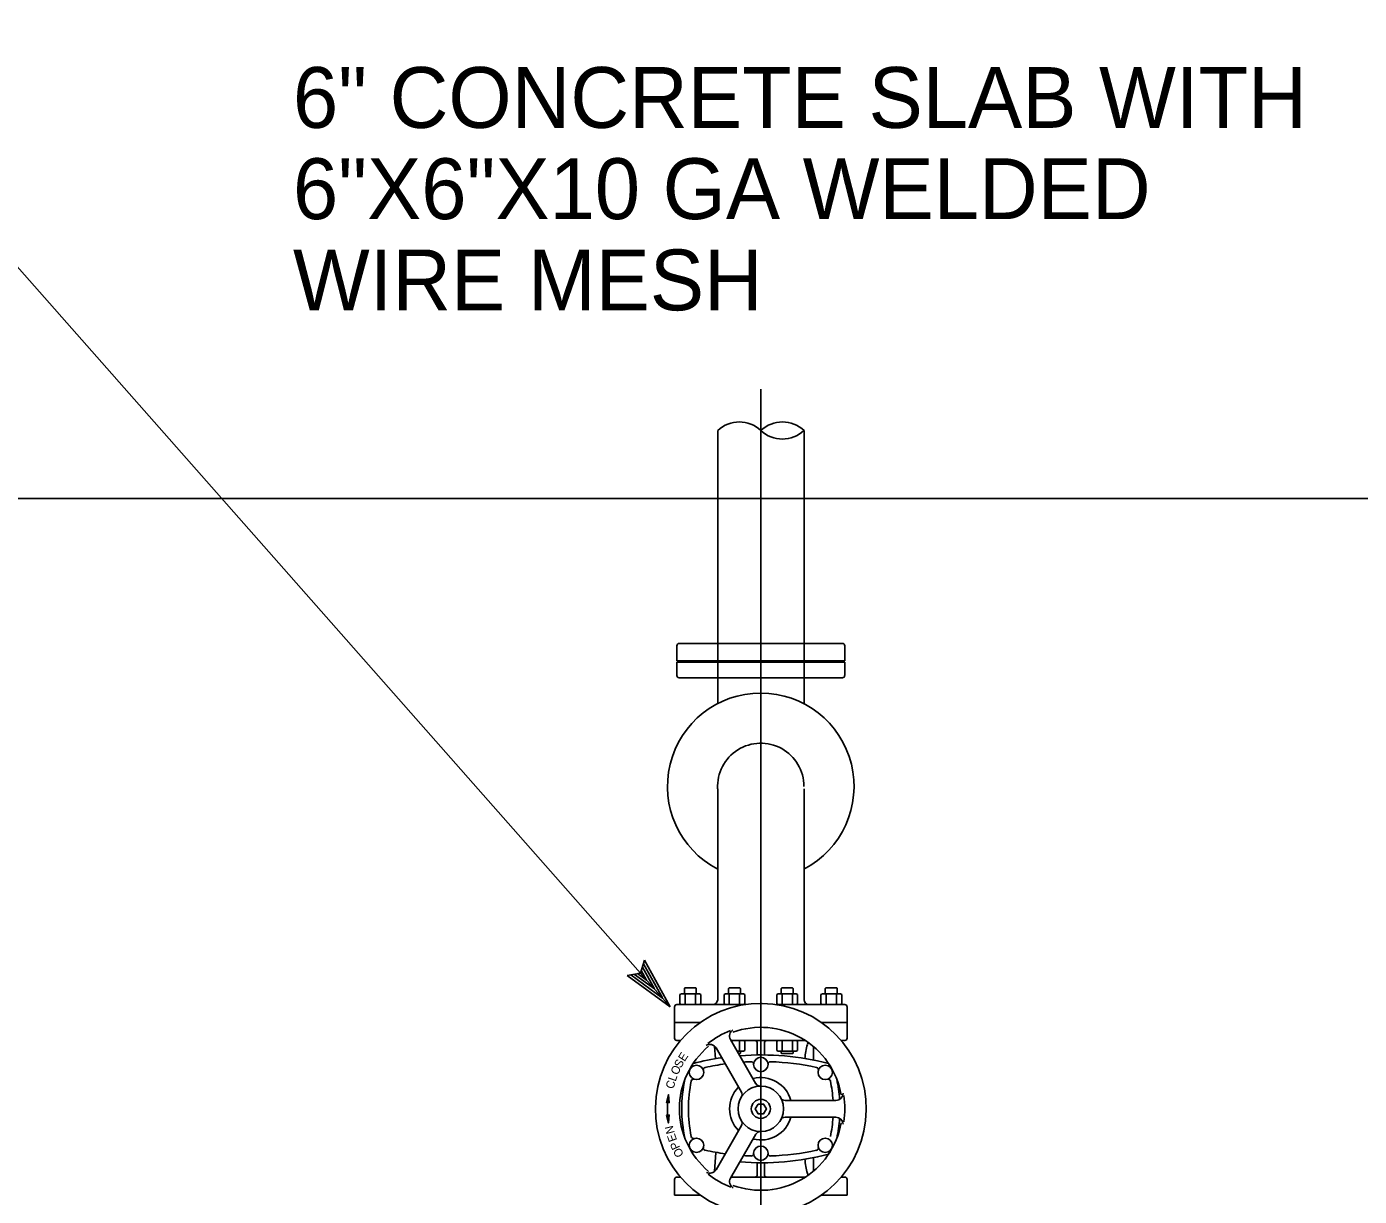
# Model space of a CAD drawing. Extents: x -1680 to 1155, y -802 to 799.
# Drawn here: x 316.4 to 469.8, y -393.2 to -258.6 of the extents above; entities that cross this region are included whole.
import ezdxf

# ---------------------------------------------------------------- set-up
doc = ezdxf.new("R2010")
doc.units = 0
doc.layers.add('Misc CnstDet(22)', color=7, linetype='Continuous')

msp = doc.modelspace()

# ---------------------------------------------------------------- linework, layer by layer
at = {"layer": 'Misc CnstDet(22)'}
for p, q in [((400.86, -548.25), (400.86, -300.3)), ((395.9, -318.16), (395.9, -305.06)), ((405.84, -318.16), (405.84, -305.06)), ((212.09, -312.88), (439.15, -312.88)), ((439.15, -312.88), (565.93, -312.88)), ((395.9, -318.16), (395.9, -336.5)), ((405.84, -318.16), (405.84, -336.5)), ((391.48, -329.56), (395.88, -329.56)), ((408.4, -329.56), (395.88, -329.56)), ((408.4, -329.56), (410.25, -329.56)), ((391.2, -329.84), (391.2, -331.58)), ((410.53, -329.84), (410.53, -331.58)), ((391.2, -331.58), (405.54, -331.58)), ((391.2, -331.72), (391.2, -333.26)), ((391.2, -331.72), (405.25, -331.72)), ((405.25, -331.72), (410.52, -331.72)), ((405.54, -331.58), (410.53, -331.58)), ((410.52, -331.72), (410.52, -333.26)), ((391.46, -333.52), (395.37, -333.52)), ((406.37, -333.52), (395.37, -333.52)), ((410.26, -333.52), (406.36, -333.52)), ((395.9, -364.45), (395.9, -346.29)), ((405.84, -364.45), (405.84, -346.29)), ((395.9, -370.58), (395.9, -364.45)), ((405.84, -370.58), (405.84, -364.45)), ((387.48, -366.03), (387.01, -367.51)), ((389.54, -370.37), (387.37, -366.45)), ((390.45, -371.41), (387.48, -366.03)), ((387.48, -366.03), (387.48, -366.03)), ((387.01, -367.51), (385.48, -367.8)), ((385.48, -367.8), (385.48, -367.8)), ((385.48, -367.8), (390.45, -371.41)), ((385.89, -367.72), (389.54, -370.38)), ((386.31, -367.66), (388.63, -369.34)), ((386.69, -367.57), (387.71, -368.31)), ((387.71, -368.31), (387.11, -367.22)), ((388.63, -369.34), (387.23, -366.81)), ((392.13, -369.2), (392.07, -369.27)), ((392.07, -369.27), (392.07, -369.9)), ((392.13, -369.2), (393.38, -369.2)), ((393.38, -369.2), (393.44, -369.27)), ((393.44, -369.27), (393.44, -369.9)), ((397.21, -369.2), (397.14, -369.27)), ((397.14, -369.27), (397.14, -369.9)), ((397.21, -369.2), (398.46, -369.2)), ((398.46, -369.2), (398.52, -369.27)), ((398.52, -369.27), (398.52, -369.9)), ((403.28, -369.2), (403.22, -369.27)), ((403.22, -369.27), (403.22, -369.9)), ((403.28, -369.2), (404.53, -369.2)), ((404.53, -369.2), (404.6, -369.27)), ((404.6, -369.27), (404.6, -369.9)), ((408.36, -369.2), (408.29, -369.27)), ((408.29, -369.27), (408.29, -369.9)), ((408.36, -369.2), (409.61, -369.2)), ((409.61, -369.2), (409.67, -369.27)), ((409.67, -369.27), (409.67, -369.9)), ((391.21, -371.13), (399.04, -371.13)), ((391.56, -369.99), (391.72, -369.9)), ((391.56, -369.99), (391.56, -371.04)), ((391.56, -371.04), (391.72, -371.13)), ((391.72, -369.9), (393.79, -369.9)), ((391.72, -371.13), (393.79, -371.13)), ((392.16, -369.99), (392.16, -371.04)), ((393.35, -369.99), (393.35, -371.04)), ((393.95, -369.99), (393.79, -369.9)), ((393.95, -371.04), (393.79, -371.13)), ((393.95, -369.99), (393.95, -371.04)), ((396.64, -369.99), (396.8, -369.9)), ((396.64, -369.99), (396.64, -371.04)), ((396.64, -371.04), (396.8, -371.13)), ((396.8, -369.9), (398.87, -369.9)), ((396.8, -371.13), (398.87, -371.13)), ((397.23, -369.99), (397.23, -371.04)), ((398.43, -369.99), (398.43, -371.04)), ((399.03, -369.99), (398.87, -369.9)), ((399.03, -371.04), (398.87, -371.13)), ((399.03, -369.99), (399.03, -371.04)), ((402.69, -371.13), (410.53, -371.13)), ((402.71, -369.99), (402.87, -369.9)), ((402.71, -369.99), (402.71, -371.04)), ((402.71, -371.04), (402.87, -371.13)), ((402.87, -369.9), (404.94, -369.9)), ((402.87, -371.13), (404.94, -371.13)), ((403.31, -369.99), (403.31, -371.04)), ((404.51, -369.99), (404.51, -371.04)), ((405.1, -369.99), (404.94, -369.9)), ((405.1, -371.04), (404.94, -371.13)), ((405.1, -369.99), (405.1, -371.04)), ((407.79, -369.99), (407.95, -369.9)), ((407.79, -369.99), (407.79, -371.04)), ((407.79, -371.04), (407.95, -371.13)), ((407.95, -369.9), (410.02, -369.9)), ((407.95, -371.13), (410.02, -371.13)), ((408.39, -369.99), (408.39, -371.04)), ((409.58, -369.99), (409.58, -371.04)), ((410.18, -369.99), (410.02, -369.9)), ((410.18, -371.04), (410.02, -371.13)), ((410.18, -369.99), (410.18, -371.04)), ((390.45, -371.41), (390.45, -371.41)), ((390.94, -373.2), (390.94, -371.41)), ((410.8, -373.2), (410.8, -371.41)), ((390.94, -373.2), (390.94, -374.99)), ((390.94, -373.2), (393.89, -373.2)), ((390.94, -373.2), (393.89, -373.2)), ((390.94, -373.72), (390.94, -374.99)), ((407.85, -373.2), (410.8, -373.2)), ((407.85, -373.2), (410.8, -373.2)), ((410.8, -373.2), (410.8, -374.99)), ((391.21, -375.27), (391.62, -375.27)), ((391.56, -375.27), (391.56, -375.34)), ((400.31, -380.24), (397.38, -375.16)), ((405.99, -375.27), (397.44, -375.27)), ((398.87, -375.27), (397.44, -375.27)), ((398.43, -376.41), (398.43, -375.37)), ((399.03, -375.36), (398.87, -375.27)), ((399.03, -376.41), (399.03, -375.36)), ((400.46, -376.93), (400.46, -375.55)), ((401.28, -376.93), (401.28, -375.55)), ((402.71, -375.36), (402.87, -375.27)), ((402.71, -376.41), (402.71, -375.36)), ((402.87, -375.27), (404.94, -375.27)), ((403.31, -376.41), (403.31, -375.37)), ((404.51, -376.41), (404.51, -375.37)), ((405.1, -375.36), (404.94, -375.27)), ((405.1, -376.41), (405.1, -375.36)), ((410.53, -375.27), (410.12, -375.27)), ((410.18, -375.27), (410.18, -375.34)), ((395.64, -377.36), (395.53, -375.92)), ((398.64, -381.2), (395.71, -376.13)), ((398.87, -376.51), (398.16, -376.51)), ((398.46, -376.78), (398.32, -376.78)), ((398.46, -376.78), (398.52, -376.72)), ((398.52, -376.72), (398.52, -376.51)), ((399.03, -376.41), (398.87, -376.51)), ((402.71, -376.41), (402.87, -376.51)), ((402.87, -376.51), (404.94, -376.51)), ((403.22, -376.72), (403.22, -376.51)), ((403.28, -376.78), (403.22, -376.72)), ((403.28, -376.78), (404.53, -376.78)), ((404.53, -376.78), (404.6, -376.72)), ((404.6, -376.72), (404.6, -376.51)), ((405.1, -376.41), (404.94, -376.51)), ((406.94, -377.51), (406.94, -375.98)), ((403.66, -382.17), (409.51, -382.17)), ((403.66, -384.1), (409.51, -384.1)), ((398.64, -385.06), (395.71, -390.14)), ((400.31, -386.03), (397.38, -391.1)), ((395.69, -388.14), (395.53, -390.35)), ((400.46, -389.34), (400.46, -390.72)), ((401.28, -389.34), (401.28, -390.72)), ((406.94, -388.75), (406.94, -390.29)), ((391.62, -391), (391.21, -391)), ((405.99, -391), (397.44, -391)), ((410.53, -391), (410.12, -391)), ((390.94, -393.07), (390.94, -391.27)), ((410.8, -393.07), (410.8, -391.27)), ((393.89, -393.07), (390.94, -393.07)), ((390.94, -393.07), (393.89, -393.07)), ((410.8, -393.07), (407.85, -393.07)), ((407.85, -393.07), (410.8, -393.07))]:
    msp.add_line(p, q, dxfattribs=at)
msp.add_lwpolyline([(390.45, -371.41), (269.3, -234.08), (260.5, -234.08)], dxfattribs=at)
for points in [[(390.32, -382.44), (390.01, -382.42), (390.23, -381.5)], [(400.55, -382.58), (400.23, -383.13), (400.55, -383.69), (401.19, -383.69), (401.51, -383.13), (401.19, -382.58)], [(390.32, -383.82), (390.01, -383.85), (390.23, -384.76)]]:
    msp.add_lwpolyline(points, close=True, dxfattribs=at)
for centre, radius in [((400.87, -378.03), 0.828), ((393.46, -378.94), 0.828), ((408.28, -378.94), 0.828), ((400.87, -383.13), 2.62), ((400.87, -383.13), 1.1), ((393.46, -387.33), 0.828), ((408.28, -387.33), 0.828), ((400.87, -388.24), 0.828)]:
    msp.add_circle(centre, radius, dxfattribs=at)
for centre, radius, start, end in [((398.39, -307.68), 3.61, 46.4429, 133.4774), ((403.36, -307.68), 3.61, 46.5406, 133.539), ((403.35, -302.45), 3.6, 226.4033, 313.6763), ((391.48, -329.84), 0.279, 90, 180), ((410.25, -329.84), 0.279, 0, 90), ((391.46, -333.26), 0.258, 180, 270), ((410.26, -333.26), 0.258, 270, 0), ((400.86, -346.02), 10.74, 297.5711, 242.4959), ((400.86, -346.02), 4.97, 0.0006, 183.0872), ((400.87, -383.13), 12.14, 89.4109, 89.3632), ((391.21, -371.41), 0.276, 90, 180), ((395.35, -370.58), 0.552, 270, 0), ((406.39, -370.58), 0.552, 180, 270), ((410.53, -371.41), 0.276, 39.9587, 90), ((410.53, -371.41), 0.276, 0, 90), ((390.66, -373.72), 0.276, 0, 11.7683), ((400.87, -383.13), 9.66, 111.1733, 129.046), ((398.1, -374.75), 0.828, 121.7915, 210), ((400.87, -383.13), 9.38, 9.8969, 110.1031), ((391.21, -374.99), 0.276, 180, 270), ((394.99, -376.54), 0.828, 30, 121.3135), ((400.18, -375.55), 0.276, 0, 90), ((401.56, -375.55), 0.276, 90, 180), ((416.65, -378.42), 10.77, 165.4239, 174.2397), ((407.13, -375.99), 0.95, 148.9584, 162.6862), ((410.53, -374.99), 0.276, 270, 0), ((400.87, -383.13), 9.38, 129.8969, 230.1031), ((400.87, -408.52), 31.59, 98.2117, 104.2666), ((400.87, -408.52), 31.59, 75.7334, 94.3855), ((394.52, -378.63), 0.276, 101.9908, 196.6074), ((400.87, -408.52), 30.83, 97.6469, 101.9908), ((400.87, -408.52), 30.83, 92.0678, 93.7076), ((399.77, -377.98), 0.276, 357.4512, 92.0678), ((401.97, -377.98), 0.276, 87.9322, 182.5489), ((400.87, -408.52), 30.83, 78.0092, 87.9322), ((407.22, -378.63), 0.276, 343.3926, 78.0092), ((407.92, -383.13), 16.15, 167.8489, 192.1511), ((407.92, -383.13), 15.39, 168.0139, 180), ((393.13, -379.99), 0.276, 72.3405, 168.0139), ((400.87, -383.13), 3.59, 15.6185, 104.3815), ((400.79, -379.96), 0.552, 210, 271.4281), ((408.61, -379.99), 0.276, 11.9861, 107.6595), ((393.82, -383.13), 15.39, 3.5967, 11.9861), ((393.82, -383.13), 16.15, 3.9315, 12.1511), ((400.87, -383.13), 10.76, 173.2861, 186.7139), ((400.87, -383.13), 3.59, 135.6185, 224.3815), ((398.16, -381.48), 0.552, 328.5719, 30), ((403.66, -381.62), 0.552, 208.5719, 270), ((409.51, -381.34), 0.828, 270, 1.3135), ((400.87, -383.13), 9.66, 351.1733, 9.046), ((407.92, -383.13), 15.39, 180, 191.9861), ((400.87, -383.13), 9.38, 249.8969, 350.1031), ((398.16, -384.79), 0.552, 330, 31.4281), ((400.87, -383.13), 3.59, 255.6185, 344.3815), ((403.66, -384.65), 0.552, 90, 151.4281), ((393.82, -383.13), 15.39, 348.0139, 356.4033), ((409.51, -384.93), 0.828, 1.7915, 90), ((393.82, -383.13), 16.15, 347.8489, 356.0685), ((393.13, -386.27), 0.276, 191.9861, 287.6595), ((400.79, -386.31), 0.552, 88.5719, 150), ((394.52, -387.64), 0.276, 163.3926, 258.0092), ((400.87, -357.75), 30.83, 258.0092, 262.3531), ((400.87, -357.75), 30.83, 272.0678, 281.9908), ((407.22, -387.64), 0.276, 281.9908, 16.6074), ((400.87, -357.75), 31.59, 265.6145, 284.2666), ((400.87, -357.75), 30.83, 266.2924, 267.9322), ((399.77, -388.29), 0.276, 267.9322, 2.5489), ((401.97, -388.29), 0.276, 177.4512, 272.0678), ((416.65, -387.85), 10.77, 185.7603, 194.5761), ((391.21, -391.27), 0.276, 90, 180), ((394.99, -389.72), 0.828, 241.7915, 330), ((400.87, -383.13), 9.66, 231.1733, 249.046), ((398.1, -391.52), 0.828, 150, 241.3135), ((400.18, -390.72), 0.276, 270, 0), ((401.56, -390.72), 0.276, 180, 270), ((407.13, -390.28), 0.95, 197.3138, 211.0416), ((410.53, -391.27), 0.276, 0, 90)]:
    msp.add_arc(centre, radius, start, end, dxfattribs=at)

# ---------------------------------------------------------------- texts
for s, height, rotation, p in [('6" CONCRETE SLAB WITH', 7, 360, (347.01, -270.23)), ('6"X6"X10 GA WELDED', 7, 360, (347.01, -280.73)), ('WIRE MESH', 7, 360, (347.01, -291.23)), ('E', 0.966, 57.3232, (392.09, -377.76)), ('O', 0.966, 66.6982, (391.32, -379.31)), ('S', 0.966, 62.0107, (391.68, -378.51)), ('C', 0.966, 76.0732, (390.83, -380.9)), ('L', 0.966, 71.3857, (391.06, -380.04)), ('N', 0.966, 104.3391, (390.96, -385.89)), ('E', 0.966, 109.3391, (391.24, -386.73)), ('P', 0.966, 114.3391, (391.6, -387.58)), ('O', 0.966, 119.3391, (392.04, -388.39))]:
    msp.add_text(s, height=height, rotation=rotation, dxfattribs=at).set_placement(p)

doc.saveas('drawing.dxf')
